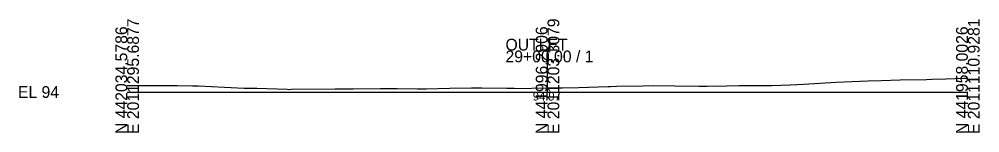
# Model space of a CAD drawing. Extents: x -26 to 1203, y -15 to 9526.
# Drawn here: x 974.3 to 1202.8, y 8990.3 to 9017.3 of the extents above; entities that cross this region are included whole.
import ezdxf

# ---------------------------------------------------------------- set-up
doc = ezdxf.new("R2010")
doc.units = 0
for name, color, linetype in [('Exist Cross Section Cell', 7, 'Continuous'), ('Exist XS Center Line Elevation Label', 7, 'Continuous'), ('Exist XS Ground Line', 7, 'Continuous')]:
    doc.layers.add(name, color=color, linetype=linetype)

msp = doc.modelspace()

# ---------------------------------------------------------------- linework, layer by layer
at = {"layer": 'Exist Cross Section Cell'}
for p, q in [((1100, 9000), (1100, 9009.86)), ((1000, 9000), (1100, 9000)), ((1100, 9000), (1200, 9000))]:
    msp.add_line(p, q, dxfattribs=at)
at = {"layer": 'Exist XS Ground Line'}
msp.add_lwpolyline([(1000, 9001.51), (1006.16, 9001.56), (1007.86, 9001.58), (1011.96, 9001.53), (1015.51, 9001.44), (1016.98, 9001.44), (1023.16, 9001.14), (1027.81, 9000.93), (1030.82, 9000.89), (1038.08, 9000.66), (1038.63, 9000.62), (1039.02, 9000.64), (1049.46, 9000.75), (1053.77, 9000.79), (1060.28, 9000.86), (1064.19, 9000.82), (1069.08, 9000.72), (1071.11, 9000.78), (1076.73, 9000.91), (1081.93, 9001.03), (1084.39, 9001), (1090.31, 9000.92), (1092.04, 9000.88), (1092.76, 9000.87), (1099.69, 9000.97), (1100, 9000.97), (1103.58, 9001.01), (1107.35, 9001.05), (1114.41, 9001.31), (1115, 9001.33), (1116.43, 9001.36), (1122.65, 9001.43), (1125.23, 9001.55), (1130.3, 9001.49), (1136.06, 9001.39), (1137.96, 9001.38), (1142.55, 9001.47), (1145.61, 9001.54), (1146.88, 9001.51), (1153.26, 9001.52), (1157.71, 9001.7), (1160.92, 9001.9), (1168.67, 9002.38), (1176.22, 9002.67), (1179.35, 9002.74), (1183.88, 9002.88), (1190.18, 9003), (1191.53, 9003.04), (1194.78, 9003.13), (1199.18, 9003.28), (1200, 9003.29)], dxfattribs=at)

# ---------------------------------------------------------------- texts
at = {"layer": 'Exist Cross Section Cell'}
for s, p in [('E 2011295.6877', (1002.8, 8990)), ('E 2011203.3079', (1102.8, 8990)), ('E 2011110.9281', (1202.8, 8990)), ('N 442034.5786', (1000, 8990)), ('N 441996.2906', (1100, 8990)), ('N 441958.0026', (1200, 8990))]:
    msp.add_text(s, height=2.8, rotation=90, dxfattribs=at).set_placement(p)
for s, p in [('OUTLET', (1090, 9009.86)), ('29+00.00 / 1', (1090, 9007.06)), ('EL 94', (974, 8998.6))]:
    msp.add_text(s, height=2.8, dxfattribs=at).set_placement(p)
at = {"layer": 'Exist XS Center Line Elevation Label'}
msp.add_text('94.97', height=2, dxfattribs=at).set_placement((1096.49, 8997.97))

doc.saveas('drawing.dxf')
